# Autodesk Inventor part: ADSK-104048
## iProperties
Shininess: 0.0
Created: 2000-11
Part Number: ADSK-104048
Description: AISI 1040 DIA. 2-1/4" x 22-1/2" LONG
Document SubType Name: Modeling
Stock Number: ADSK-104048
Density: 1 g/cm^3
Density: 0.0
Volumn: 0.0
Area: 0.0
PropertySet Name: Model Information
Control State: 0
Master: False
Checked Out: False
Author: gao
